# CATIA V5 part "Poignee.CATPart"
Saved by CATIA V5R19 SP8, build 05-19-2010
Part number: Poignée plastique
Bounding box of the stored display mesh (mm): x 30.122 to 66.573, y 0 to 173.822, z -90.177 to 2.974
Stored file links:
  E:\Catia parts\GLOCK\Poignée\Poignee.CATPart
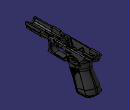
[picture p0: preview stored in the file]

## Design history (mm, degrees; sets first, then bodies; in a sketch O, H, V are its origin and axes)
Body1 (main body)
  Solid1: solid without history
